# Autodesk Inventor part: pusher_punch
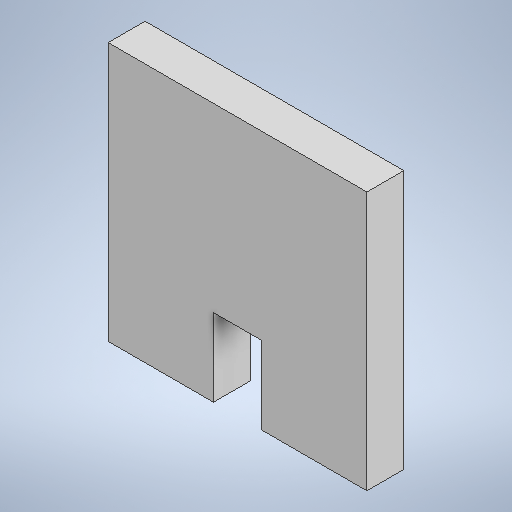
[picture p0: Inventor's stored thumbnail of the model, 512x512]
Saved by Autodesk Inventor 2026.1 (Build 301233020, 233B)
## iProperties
Created: 2026-10
Part Number: pusher_punch
Material: Generic
Document SubType Name: Modeling
Designer: alolo
Density: 1 g/cm^3
Appearance: Default
Author: alolo
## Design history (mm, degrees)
sketch "Sketch1"
  geometry: L1 (0, 0)-(65, 0); L2 (65, 0)-(65, 80); L3 (65, 80)-(0, 80); L4 (0, 80)-(0, 0)
  constraints: 8 end point, 2 parallel, 1 horizontal, 1 perpendicular
  dimensions: "d0" = 65 distance of L3.end L2.end (= slide_width); "d1" = 80 distance of L2.end L1.end
extrude "Extrusion1" new body sketch "Sketch1" distance "d2" = 130; taper "d3" = 0 deg
sketch "Sketch2"
  geometry: L1 (0, 0)-(-65, 0) reference; L2 (-38.5, 0)-(-26.5, 0); L3 (-26.5, 0)-(-26.5, 15); L4 (-26.5, 15)-(-38.5, 15); L5 (-38.5, 15)-(-38.5, 0); 3 further points
  constraints: 8 end point, 2 midpoint, 2 parallel, 1 coincident, 1 horizontal, 1 perpendicular, 1 point on line
  dimensions: "d19" = 12 distance of L4.end L3.end; "d20" = 15 distance of L2.end L3.end
extrude "Extrusion2" cut sketch "Sketch2" distance "d21" = 40; taper "d22" = 0 deg
chamfer "Chamfer6" distance "d23" = 60; stored, may be unused: second distance "d24" = 100, angle "d25" = 45 deg
chamfer "Chamfer7" distance "d26" = 15; stored, may be unused: second distance "d27" = 5, angle "d28" = 45 deg
chamfer "Chamfer8" distance "d29" = 10; stored, may be unused: second distance "d30" = 2, angle "d31" = 45 deg
chamfer "Chamfer10" distance "d35" = 5; stored, may be unused: second distance "d36" = 15, angle "d37" = 45 deg
chamfer "Chamfer11" distance "d38" = 5; stored, may be unused: second distance "d39" = 15, angle "d40" = 45 deg
sketch "Sketch3"
  geometry: L1 (-65, 0)-(-65, 80) reference; L2 (0, 80)-(0, 0) reference; L3 (-65, 80)-(0, 80); L4 (0, 80)-(0, 60); L5 (0, 60)-(-65, 60); L6 (-65, 60)-(-65, 80); 2 further points
  constraints: 8 end point, 2 parallel, 1 horizontal, 1 perpendicular, 1 point on line
  dimensions: "d41" = 20 distance of L3.end L4.end
extrude "Extrusion3" cut sketch "Sketch3" stored distance "d42" = 10; taper "d43" = 0 deg
sketch "Sketch5"
  geometry: L1 (0, 60)-(0, 2.507) reference; L2 (0, 0)-(26.5, 0) reference; L3 (0, 0)-(65, 0); L4 (65, 0)-(65, 60); L5 (65, 60)-(0, 60); L6 (0, 60)-(0, 0); 3 further points
  constraints: 8 end point, 2 parallel, 1 horizontal, 1 perpendicular
extrude "Extrusion4" cut sketch "Sketch5" distance "d45" = 125; taper "d46" = 0 deg
sketch "Sketch6"
  geometry: L1 (0, 0)-(0, 60) reference; L2 (65, 0)-(38.5, 0) reference; L3 (0, 60)-(65, 60); L4 (65, 60)-(65, 0); L5 (65, 0)-(0, 0); L6 (0, 0)-(0, 60); L7 (15, 0)-(50, 0); L8 (50, 0)-(50, 35); L9 (50, 35)-(15, 35); L10 (15, 35)-(15, 0); 4 further points
  constraints: 16 end point, 4 parallel, 2 horizontal, 2 midpoint, 2 perpendicular, 1 point on line, 1 vertical alignment
  dimensions: "d47" = 35 distance of L9.end L8.end; "d48" = 35 distance of L8.end L7.end
extrude "Extrusion5" cut sketch "Sketch6" distance "d49" = 5; taper "d50" = 0 deg
sketch "Sketch7"
  geometry: L1 (29.25, 0)-(35.75, 0); L2 (35.75, 0)-(35.75, 10.5); L3 (35.75, 10.5)-(29.25, 10.5); L4 (29.25, 10.5)-(29.25, 0); L5 (50, 35)-(15, 35) reference; L6 (38.5, 15)-(26.5, 15) reference; L7 (50, 0)-(38.5, 0) reference; L8 (26.5, 15)-(26.5, 0) reference; L9 (26.5, 0)-(15, 0) reference; L10 (38.5, 0)-(38.5, 15) reference; L11 (26.5, 0)-(38.5, 0); 5 further points
  constraints: 10 end point, 2 horizontal, 2 midpoint, 2 parallel, 1 collinear, 1 perpendicular, 1 vertical alignment
  dimensions: "d51" = 6.5 distance of L3.end L2.end; "d52" = 10.5 distance of L3.end L1.start
extrude "Extrusion6" join sketch "Sketch7" distance "d53" = 5; taper "d54" = 0 deg
body "Solid1"
other parameters: "slide_length" = 195 [user parameter], "slide_angle" = 7 deg [user parameter], "slide_width" = 65 [user parameter; used in 1 equation term], "wood_thickness" = 5 [user parameter], "aclyric_thickness" = 6 [user parameter]
